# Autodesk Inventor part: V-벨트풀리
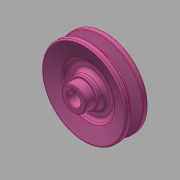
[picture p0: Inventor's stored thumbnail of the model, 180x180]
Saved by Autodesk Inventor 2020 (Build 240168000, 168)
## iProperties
Created: 2016-08
Part Number: V-벨트풀리
Material: 알루미늄 6061
Document SubType Name: Modeling
Designer: mduedu
Density: 2.71 g/cm^3
Appearance: 분홍색
Author: mduedu
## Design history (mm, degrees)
sketch "스케치1"
  geometry: L1 (0, 17.5)-(0, -9.5); L2 (10, 9.5)-(35, 9.5); L3 (35, 9.5)-(35, 4.825); L4 (35, 4.825)-(26, 2.074); L5 (26, 2.074)-(26, 0); L6 (0, 0)-(26, 0); L7 (0, -9.5)-(35, -9.5); L8 (35, -9.5)-(35, -4.825); L9 (35, -4.825)-(26, -2.074); L10 (26, -2.074)-(26, 0); L11 (32.3, 9.5)-(32.3, -9.5); L12 (10, 9.5)-(10, 17.5); L13 (10, 17.5)-(0, 17.5); 3 further points
  constraints: 26 end point, 7 point on line, 5 perpendicular, 3 symmetric about line, 2 parallel, 1 coincident, 1 horizontal alignment, 1 vertical
  dimensions: "d2" = 70 diameter of L8 L1; "d4" = 6.3 distance between parallel lines of L10 L11; "d5" = 2.7 distance between parallel lines of L11 L8; "d6" = 8 distance of point (32.3, -4) point (32.3, 4); "d7" = 34 deg angle of L9 L4; "d30" = 9.5 distance between parallel lines of L7 L6; "d32" = 27 distance between parallel lines of L13 L7; "d33" = 20 diameter of L12 L1
revolve "회전1" sketch "스케치1" stored, may be unused: angle "d8" = 90 deg
sketch "스케치2"
  geometry: L1 (-2, 0)-(2, 0); L2 (2, 0)-(2, 7.3); L3 (2, 7.3)-(-2, 7.3); L4 (-2, 7.3)-(-2, 0); C1 r 5.5 at (0, 0); 2 further points
  constraints: 8 end point, 2 coincident, 2 parallel, 1 centre point, 1 horizontal, 1 midpoint, 1 perpendicular
  dimensions: "d9" = 11 diameter of C1; "d11" = 4 distance of L2.end L3.end; "d34" = 12.8 dimension on C1 L3
extrude "돌출1" cut sketch "스케치2" extent not by distance; stored distance "d13" = 10; taper "d14" = 0 deg
sketch "스케치3"
  geometry: L1 (35, 4.825)-(26, 2.074) reference; L2 (26, 2.074)-(26, -2.074) reference; L3 (0, 0)-(26, 0); L4 (35, 9.5)-(35, 4.825) reference; L5 (-35, 9.5)-(35, 9.5) reference; L6 (35, 9.5)-(21, 5.22); L7 (21, 5.22)-(21, 3); L8 (21, 3)-(12, 3); L9 (12, 3)-(12, 9.5); L10 (0, 9.5)-(0, -9.5); L11 (5.123, -9.5)-(-5.5, -9.5) reference; L12 (12, 9.5)-(35, 9.5)
  constraints: 14 end point, 3 midpoint, 2 parallel, 2 perpendicular, 2 point on line, 1 collinear, 1 horizontal
  dimensions: "d15" = 3 distance between parallel lines of L3 L8; "d17" = 42 diameter of L7 L10; "d18" = 24 diameter of L9 L10
revolve "회전2" sketch "스케치3" stored, may be unused: angle "d19" = 90 deg
fillet "모깎기1" dims "d20" = 0.5, "d21" = 1, "d22" = 1
fillet "모깎기2" dims "d23" = 3
fillet "모깎기3" dims "d24" = 3
fillet "모깎기4" dims "d25" = 3
chamfer "모따기1" distance "d26" = 0.5; stored, may be unused: second distance "d27" = 2, angle "d28" = 45 deg
fillet "모깎기5" dims "d29" = 1
node "작업 평면1"
sketch "스케치4"
  geometry: L1 (-9.5, 17.5)-(9.5, 17.5) reference; 2 further points
  constraints: 1 vertical alignment
  dimensions: "d41" = 4 distance from line of L1 point (0, 13.5)
hole "구멍1" sketch "스케치4" at (0, 13.5) diameter "d42" = 2.459; stored, may be unused: countersink angle "d46" = 90 deg, drill point angle "d48" = 118 deg; dims "d43" = 6, "d44" = 4, "d45" = 2, "d47" = 8
node "작업축1"
node "솔리드1"
mirror "대칭1"
